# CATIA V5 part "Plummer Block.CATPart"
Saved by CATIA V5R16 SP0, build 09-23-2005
Part number: Plummer Block
Bounding box of the stored display mesh (mm): x -27 to 27, y -2.75 to 2.75, z -26.982 to 26.982
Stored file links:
  C:\V5_education\CATIA Data\ASD\Power Transmission Gear Assembly\Assembly Data\Plummer Block.CATPart
  C:\V5_education\CATIA Data\ASD\Power Transmission Gear Assembly\Assembly Data\Power Transmission Gear Assembly.CATProduct
  C:\V5_education\CATIA Data\ASD\Power Transmission Gear Assembly\Assembly Data\Power Transmission Gear.CATPart
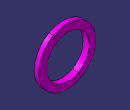
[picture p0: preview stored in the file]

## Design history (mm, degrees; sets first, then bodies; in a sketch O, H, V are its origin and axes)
Set1
  DatumSurface1: linked copy from another document
Set2 "Reference Data"
  Point1 "Center Point": (0, 0, 0)
Body1 (main body)
  Sketch1 on yz-plane, origin (0, 0, 0), H (0, 1, 0), V (0, 0, 1)
    axis line L1 (0, 0) -> (70.7713, 0)
    construction line L2 (0, 0) -> (0, 56.3698)
    point P3 (-2.75, 20)
    line L3 (-2.75, 20) -> (2.75, 20)
    point P4 (2.75, 20)
    line L4 (2.75, 20) -> (2, 27)
    point P5 (2, 27)
    line L5 (2, 27) -> (-2, 27)
    point P6 (-2, 27)
    line L6 (-2, 27) -> (-2.75, 20)
    distance L3 H = 20
    distance L5 H = 27
    distance P3 P4 = 5.5
    distance P6 P5 = 4
    horizontal: L1 H, L3 H, L5 H
    vertical: L2 V
    symmetry: L6 L4 L2
  Shaft1: profile Sketch1, axis Sketch1.L1, angle 360
  AssyPrtSPLIT1: SplitPlane DatumSurface1, _MechModInactiveResultOUT result of AssyPrtSPLIT1, deactivated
